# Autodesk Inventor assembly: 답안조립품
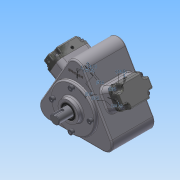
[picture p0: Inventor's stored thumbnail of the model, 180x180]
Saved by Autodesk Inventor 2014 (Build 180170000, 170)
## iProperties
Created: 2015-06
Part Number: 답안조립품
Document SubType Name: Assembly
Designer: Administrator
Mass: 5318.58 g
Surface Area: 2414.93 cm^2
Volume: 1564.62 cm^3
Density: 3.39928 g/cm^3
Author: Administrator
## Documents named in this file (20)
- C:\Users\Administrator\Desktop\350605V1031\답안조립품.iam
- C:\Users\Administrator\Desktop\350605V1031\본체.ipt
- C:\Users\Administrator\Desktop\350605V1031\편심축.ipt
- C:\Users\Administrator\Desktop\350605V1031\앞커버.ipt
- C:\Users\Administrator\Desktop\350605V1031\베어링 NA 4904.ipt
- 베어링 NA 4904.ipt
- C:\Users\Administrator\Desktop\350605V1031\오일실.ipt
- 오일실.ipt
- C:\Users\Administrator\Desktop\350605V1031\M6x0.7x20.ipt
- M6x0.7x20.ipt
- C:\Users\Administrator\Desktop\350605V1031\슬라이드.ipt
- C:\Users\Administrator\Desktop\350605V1031\부시.ipt
- C:\Users\Administrator\Desktop\350605V1031\헤더커버.ipt
- 헤더커버.ipt
- C:\Users\Administrator\Desktop\350605V1031\M4x0.5x16.ipt
- M4x0.5x16.ipt
- C:\Users\Administrator\Desktop\350605V1031\8-스프링.ipt
- C:\Users\Administrator\Desktop\350605V1031\9-스프링.ipt
- C:\Users\Administrator\Desktop\350605V1031\10-스프링.ipt
- C:\Users\Administrator\Desktop\350605V1031\11-스프링.ipt
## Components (18 placed, 7 different names)
1. 8-스프링:1
2. 9-스프링:1
3. 10-스프링:1
4. 11-스프링:1
5. M6x0.7x20:1
6. M6x0.7x20:2
7. M6x0.7x20:3
8. M6x0.7x20:4
9. 헤더커버:1
10. M4x0.5x16:1
11. M4x0.5x16:2
12. M4x0.5x16:3
13. M4x0.5x16:4
14. 헤더커버:2
15. M4x0.5x16:5
16. M4x0.5x16:6
17. M4x0.5x16:7
18. M4x0.5x16:8
